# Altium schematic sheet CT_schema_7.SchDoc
size 277 x 170 mm
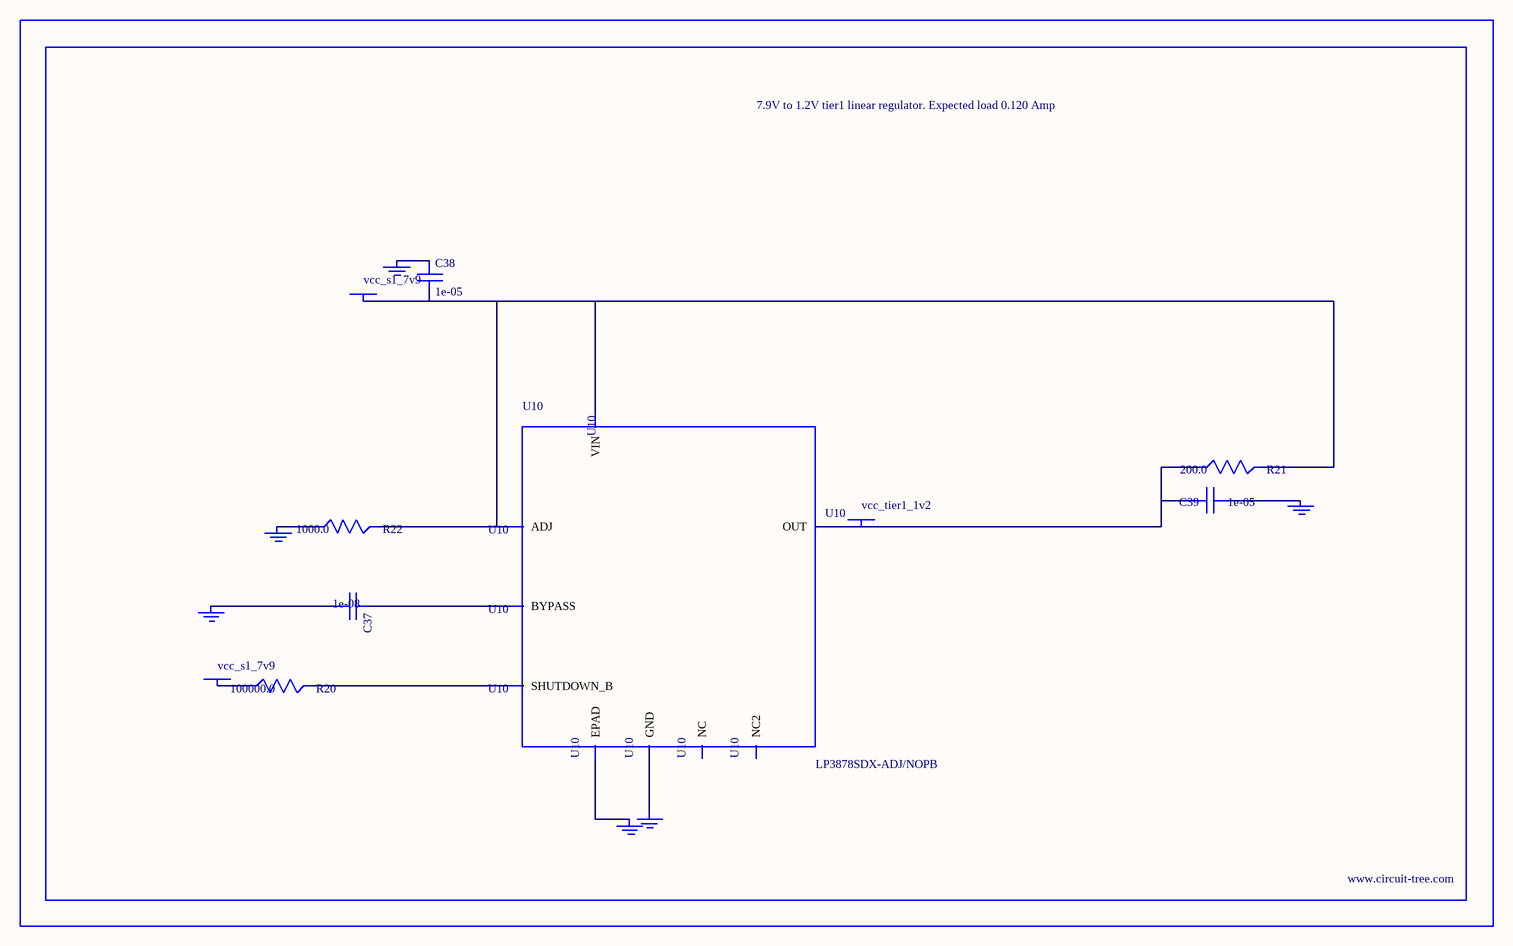
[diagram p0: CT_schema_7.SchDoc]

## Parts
BORDER6  (no value)
C37  1e-08  [C0402]
C38  1e-05  [C1206]
C39  1e-05  [C0805]
GND_INSTANCE_6_0  (no value)
GND_INSTANCE_6_1  (no value)
GND_INSTANCE_6_2  (no value)
GND_INSTANCE_6_3  (no value)
GND_INSTANCE_6_4  (no value)
GND_INSTANCE_6_5  (no value)
POWER_INSTANCE_6_0  vcc_s1_7v9
POWER_INSTANCE_6_1  vcc_s1_7v9
POWER_INSTANCE_6_2  vcc_tier1_1v2
R20  100000.0  [R0603]
R21  200.0  [R0603]
R22  1000.0  [R0603]
U10  LP3878SDX-ADJ/NOPB  [WSON-8]

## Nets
NetC37_1: C37.1 U10.1(BYPASS)
NetC37_2: C37.2 GND_INSTANCE_6_0.0(GND)
NetC38_1: C38.1 GND_INSTANCE_6_1.0(GND)
NetC38_2: C38.2 POWER_INSTANCE_6_0.0(PWR) R21.2 R22.2 U10.4(VIN) U10.6(ADJ)
NetC39_1: C39.1 GND_INSTANCE_6_2.0(GND)
NetC39_2: C39.2 POWER_INSTANCE_6_2.0(PWR) R21.1 U10.5(OUT)
NetGND_INSTANCE_6_3_0: GND_INSTANCE_6_3.0(GND) R22.1
NetGND_INSTANCE_6_4_0: GND_INSTANCE_6_4.0(GND) U10.PAD(EPAD)
NetGND_INSTANCE_6_5_0: GND_INSTANCE_6_5.0(GND) U10.3(GND)
NetPOWER_INSTANCE_6_1_0: POWER_INSTANCE_6_1.0(PWR) R20.1
NetR20_2: R20.2 U10.8(SHUTDOWN_B)

Not connected (* = marked no-connect by the designer): U10 2(NC) 7(NC2)

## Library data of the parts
BORDER6 = BORDER_PAGE6
C37 = C0402C103K3RAC
C38 = C1206C106K3RACTU
C39 = GRM219R60J106ME19D
GND_INSTANCE_6_0-GND_INSTANCE_6_5 = GND
POWER_INSTANCE_6_0-POWER_INSTANCE_6_2 = PWR
R20 = RC0603JR-07100KL
R21 = RC0603JR-07200RL
R22 = RC0603JR-071KL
